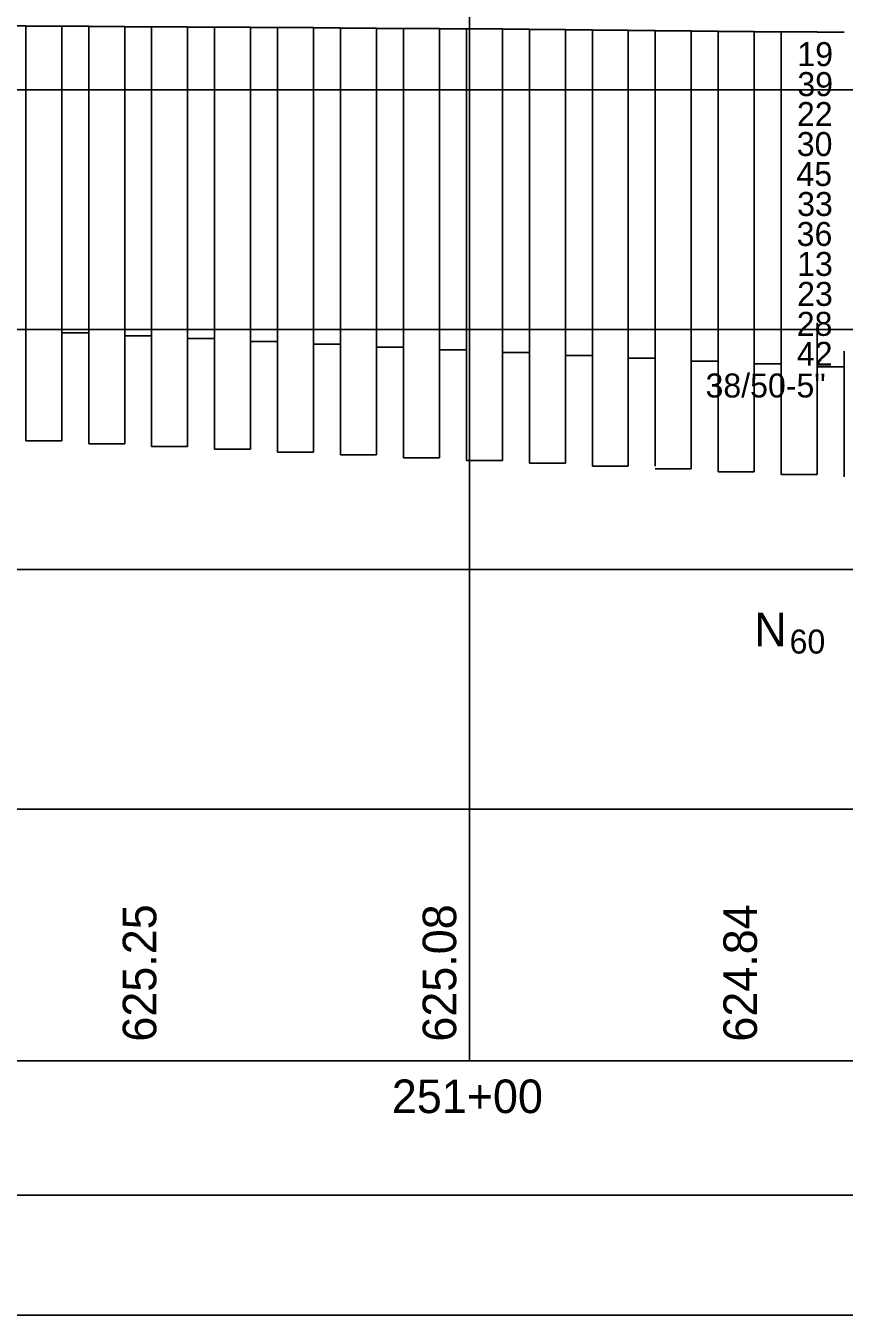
# Model space of a CAD drawing. Extents: x -2280229 to 1306, y -58886 to 440.
# Drawn here: x 248 to 316.2, y 0 to 107.6 of the extents above; entities that cross this region are included whole.
import ezdxf

# ---------------------------------------------------------------- set-up
doc = ezdxf.new("R2010")
doc.units = 0
for name, color, linetype in [('BR_P_Sub_Deep_Object', 7, 'Continuous'), ('GT_Project_Text', 7, 'Continuous'), ('SC_Scratch1', 7, 'Continuous'), ('SC_Scratch2', 7, 'Continuous'), ('SC_Scratch3', 7, 'Continuous'), ('SC_Scratch5', 7, 'Continuous'), ('SC_Scratch9', 7, 'Continuous'), ('SH_Minor_Grid_Line', 7, 'Continuous')]:
    doc.layers.add(name, color=color, linetype=linetype)

msp = doc.modelspace()

# ---------------------------------------------------------------- linework, layer by layer
at = {"layer": 'BR_P_Sub_Deep_Object'}
for p, q in [((245.73, 107.55), (247.98, 107.55)), ((247.98, 107.55), (247.98, 72.93)), ((247.98, 107.53), (250.98, 107.53)), ((250.98, 107.53), (250.98, 72.93)), ((250.98, 107.52), (253.23, 107.52)), ((253.23, 107.52), (253.23, 72.69)), ((253.23, 107.5), (256.23, 107.5)), ((256.23, 107.5), (256.23, 72.69)), ((256.23, 107.48), (258.48, 107.48)), ((258.48, 107.48), (258.48, 72.46)), ((258.48, 107.47), (261.48, 107.47)), ((261.48, 107.47), (261.48, 72.46)), ((261.48, 107.45), (263.73, 107.45)), ((263.73, 107.45), (263.73, 72.23)), ((263.73, 107.43), (266.73, 107.43)), ((266.73, 107.43), (266.73, 72.23)), ((266.73, 107.41), (268.98, 107.41)), ((268.98, 107.41), (268.98, 71.99)), ((268.98, 107.4), (271.98, 107.4)), ((271.98, 107.4), (271.98, 71.99)), ((271.98, 107.38), (274.23, 107.38)), ((274.23, 107.38), (274.23, 71.76)), ((274.23, 107.36), (277.23, 107.36)), ((277.23, 107.36), (277.23, 71.76)), ((277.23, 107.34), (279.48, 107.34)), ((279.48, 107.34), (279.48, 71.52)), ((279.48, 107.33), (282.48, 107.33)), ((282.48, 107.33), (282.48, 71.52)), ((282.48, 107.31), (284.73, 107.31)), ((284.73, 107.31), (284.73, 71.29)), ((284.73, 107.29), (287.73, 107.29)), ((287.73, 107.29), (287.73, 71.29)), ((287.73, 107.26), (289.98, 107.26)), ((289.98, 107.26), (289.98, 71.06)), ((289.98, 107.24), (292.98, 107.24)), ((292.98, 107.24), (292.98, 71.06)), ((292.98, 107.21), (295.23, 107.21)), ((295.23, 107.21), (295.23, 70.82)), ((295.23, 107.19), (298.23, 107.19)), ((298.23, 107.19), (298.23, 70.82)), ((298.23, 107.16), (300.48, 107.16)), ((300.48, 107.16), (300.48, 70.82)), ((300.48, 107.14), (303.48, 107.14)), ((303.48, 107.14), (303.48, 70.59)), ((303.48, 107.11), (305.73, 107.11)), ((305.73, 107.11), (305.73, 70.35)), ((305.73, 107.09), (308.73, 107.09)), ((308.73, 107.09), (308.73, 70.35)), ((308.73, 107.06), (310.98, 107.06)), ((310.98, 107.06), (310.98, 70.12)), ((310.98, 107.04), (313.98, 107.04)), ((313.98, 107.02), (316.23, 107.02)), ((253.23, 81.93), (250.98, 81.93)), ((313.98, 82.77), (313.98, 70.12)), ((258.48, 81.69), (256.23, 81.69)), ((263.73, 81.46), (261.48, 81.46)), ((268.98, 81.23), (266.73, 81.23)), ((274.23, 80.99), (271.98, 80.99)), ((279.48, 80.76), (277.23, 80.76)), ((284.73, 80.52), (282.48, 80.52)), ((289.98, 80.29), (287.73, 80.29)), ((295.23, 80.06), (292.98, 80.06)), ((300.48, 79.82), (298.23, 79.82)), ((316.23, 80.4), (316.23, 69.93)), ((305.73, 79.59), (303.48, 79.59)), ((310.98, 79.35), (308.73, 79.35)), ((316.23, 79.12), (313.98, 79.12)), ((250.98, 72.93), (247.98, 72.93)), ((256.23, 72.69), (253.23, 72.69)), ((261.48, 72.46), (258.48, 72.46)), ((266.73, 72.23), (263.73, 72.23)), ((271.98, 71.99), (268.98, 71.99)), ((277.23, 71.76), (274.23, 71.76)), ((282.48, 71.52), (279.48, 71.52)), ((287.73, 71.29), (284.73, 71.29)), ((292.98, 71.06), (289.98, 71.06)), ((298.23, 70.82), (295.23, 70.82)), ((303.48, 70.59), (300.48, 70.59)), ((308.73, 70.35), (305.73, 70.35)), ((313.98, 70.12), (310.98, 70.12))]:
    msp.add_line(p, q, dxfattribs=at)
at = {"layer": 'GT_Project_Text'}
msp.add_lwpolyline([(0, 0), (680, 0), (680, 440), (0, 440)], close=True, dxfattribs=at)
at = {"layer": 'SC_Scratch1'}
msp.add_lwpolyline([(30, 430), (670, 430), (670, 10), (30, 10)], close=True, dxfattribs=at)
at = {"layer": 'SC_Scratch3'}
msp.add_line((311.68, 57.19), (311.68, 57.19), dxfattribs=at)
at = {"layer": 'SC_Scratch5'}
msp.add_line((603.01, 21.22), (45.43, 21.22), dxfattribs=at)
at = {"layer": 'SH_Minor_Grid_Line'}
for p, q in [((284.98, 21.22), (284.98, 162.21)), ((45.43, 102.21), (603.01, 102.21)), ((45.43, 82.21), (603.01, 82.21)), ((45.43, 62.21), (603.01, 62.21)), ((45.43, 42.21), (603.01, 42.21))]:
    msp.add_line(p, q, dxfattribs=at)

# ---------------------------------------------------------------- texts
at = {"layer": 'SC_Scratch2'}
for s, p in [('19', (312.33, 104.19)), ('39', (312.33, 101.69)), ('22', (312.29, 99.19)), ('30', (312.28, 96.69)), ('45', (312.25, 94.19)), ('33', (312.31, 91.69)), ('36', (312.27, 89.19)), ('13', (312.31, 86.69)), ('23', (312.31, 84.19)), ('28', (312.28, 81.69)), ('42', (312.29, 79.19)), ('38/50-5"', (304.67, 76.55))]:
    msp.add_text(s, height=2, dxfattribs=at).set_placement(p)
at = {"layer": 'SC_Scratch3'}
for s, height, p in [('N', 2.8, (308.73, 55.79)), ('60', 2, (311.68, 55.19))]:
    msp.add_text(s, height=height, dxfattribs=at).set_placement(p)
at = {"layer": 'SC_Scratch9'}
for s, p in [('625.25', (258.87, 22.82)), ('625.08', (283.88, 22.82)), ('624.84', (308.96, 22.82))]:
    msp.add_text(s, height=2.8, rotation=90, dxfattribs=at).set_placement(p)
msp.add_text('251+00', height=2.8, dxfattribs=at).set_placement((278.51, 16.86))

doc.saveas('drawing.dxf')
